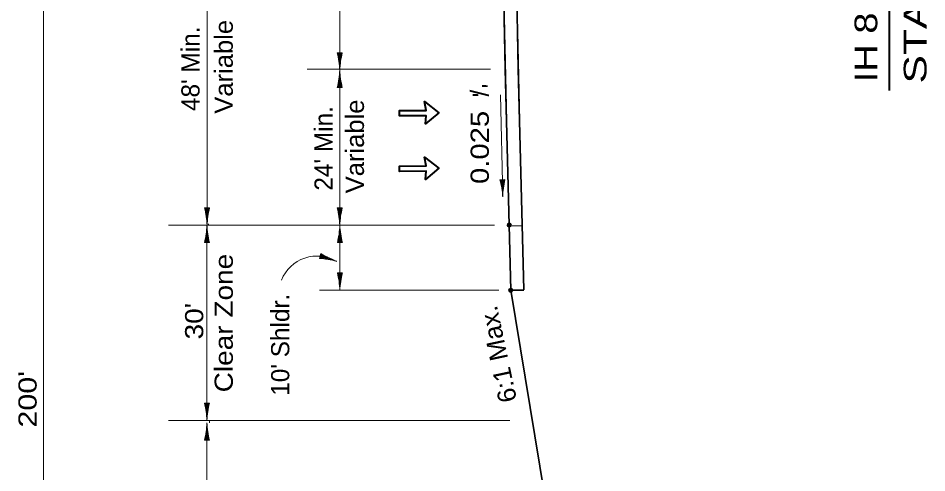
# Model space of a CAD drawing. Extents: x 2363427 to 2368559, y 6957299 to 6980140.
# Drawn here: x 2364676 to 2365376, y 6958581 to 6958931 of the extents above; entities that cross this region are included whole.
import ezdxf
from ezdxf.enums import TextEntityAlignment as Align

# ---------------------------------------------------------------- set-up
doc = ezdxf.new("R2010")
doc.units = 0
doc.header["$LTSCALE"] = 5.6
doc.header["$PDMODE"] = 32
doc.header["$PDSIZE"] = 2.8
for name, color, linetype, lineweight in [('3', 7, 'Continuous', 35), ('4', 7, 'Continuous', 13), ('40', 7, 'Continuous', 35), ('6', 7, 'Continuous', 13), ('8', 7, 'Continuous', 13)]:
    doc.layers.add(name, color=color, linetype=linetype, lineweight=lineweight)

msp = doc.modelspace()

# ---------------------------------------------------------------- linework, layer by layer
at = {"layer": '3'}
for p, q in [((2365057.76, 6959071.646), (2365061.35, 6958891.693)), ((2365061.348, 6958891.755), (2365064.48, 6958771.889)), ((2365054.484, 6958771.627), (2365055.653, 6958721.475)), ((2365064.481, 6958771.861), (2365065.65, 6958721.709)), ((2365065.653, 6958721.593), (2365055.65, 6958721.593)), ((2365055.653, 6958721.475), (2365118.982, 6958338.693))]:
    msp.add_line(p, q, dxfattribs=at)
at = {"layer": '3', "lineweight": 13}
for p, q in [((2365040.062, 6958891.447), (2364898.916, 6958891.447)), ((2365043.199, 6958771.447), (2364792.272, 6958771.447)), ((2365046.336, 6958721.447), (2364908.326, 6958721.447)), ((2365054.844, 6958621.447), (2364792.272, 6958621.447))]:
    msp.add_line(p, q, dxfattribs=at)
at = {"layer": '3'}
msp.add_lwpolyline([(2365047.761, 6959071.447), (2365051.351, 6958891.493), (2365054.484, 6958771.627)], dxfattribs=at)
at = {"layer": '3', "lineweight": 13}
for points in [[(2365054.483, 6958770.888), (2365064.398, 6958771.059), (2365058.919, 6959012.302), (2365048.975, 6959011.836)], [(2365055.653, 6958721.475), (2365065.65, 6958721.709), (2365064.398, 6958771.059), (2365054.483, 6958770.888)]]:
    msp.add_lwpolyline(points, close=True, dxfattribs=at)
msp.add_lwpolyline([(2365054.484, 6958771.627), (2365054.414, 6958771.773), (2365054.484, 6958771.627)], dxfattribs=at)
at = {"layer": '3'}
for p in [(2365054.484, 6958771.627), (2365055.653, 6958721.475)]:
    msp.add_point(p, dxfattribs=at)
at = {"layer": '4', "lineweight": 40}
msp.add_line((2365347.244, 6958874.931), (2365347.244, 6959337.074), dxfattribs=at)
at = {"layer": '4'}
for p, q in [((2365049.461, 6958793.173), (2365047.85, 6958871.793)), ((2365047.274, 6958806.443), (2365051.103, 6958806.521)), ((2365047.624, 6958806.449), (2365047.656, 6958804.865)), ((2365048.124, 6958806.461), (2365048.211, 6958802.185)), ((2365048.624, 6958806.471), (2365048.774, 6958799.123)), ((2365049.123, 6958806.481), (2365049.38, 6958793.919)), ((2365049.623, 6958806.491), (2365049.8, 6958797.883)), ((2365050.123, 6958806.501), (2365050.222, 6958801.641)), ((2365050.623, 6958806.511), (2365050.672, 6958804.131)), ((2364821.826, 6958758.135), (2364821.826, 6958770.699)), ((2364924.116, 6958758.135), (2364924.116, 6958770.699)), ((2364821.326, 6958758.135), (2364821.326, 6958766.745)), ((2364822.326, 6958758.135), (2364822.326, 6958765.485)), ((2364923.616, 6958758.135), (2364923.616, 6958766.745)), ((2364924.616, 6958758.135), (2364924.616, 6958765.485)), ((2364823.676, 6958758.135), (2364819.846, 6958758.135)), ((2364820.326, 6958758.135), (2364820.326, 6958760.517)), ((2364820.826, 6958758.135), (2364820.826, 6958762.997)), ((2364822.826, 6958758.135), (2364822.826, 6958762.411)), ((2364823.326, 6958758.135), (2364823.326, 6958759.72)), ((2364925.966, 6958758.135), (2364922.136, 6958758.135)), ((2364922.616, 6958758.135), (2364922.616, 6958760.517)), ((2364923.116, 6958758.135), (2364923.116, 6958762.997)), ((2364925.116, 6958758.135), (2364925.116, 6958762.411)), ((2364925.616, 6958758.135), (2364925.616, 6958759.72)), ((2364908.365, 6958745.982), (2364909.53, 6958749.631)), ((2364908.472, 6958746.315), (2364909.982, 6958745.833)), ((2364908.624, 6958746.792), (2364912.698, 6958745.491)), ((2364908.776, 6958747.268), (2364915.777, 6958745.031)), ((2364908.928, 6958747.745), (2364920.896, 6958743.921)), ((2364909.08, 6958748.221), (2364917.282, 6958745.601)), ((2364909.232, 6958748.697), (2364913.864, 6958747.217)), ((2364909.384, 6958749.173), (2364911.653, 6958748.449)), ((2364922.136, 6958734.758), (2364925.966, 6958734.758)), ((2364922.486, 6958734.758), (2364922.486, 6958733.173)), ((2364922.986, 6958734.758), (2364922.986, 6958730.481)), ((2364923.486, 6958734.758), (2364923.486, 6958727.408)), ((2364923.986, 6958734.758), (2364923.986, 6958722.194)), ((2364924.486, 6958734.758), (2364924.486, 6958726.149)), ((2364924.986, 6958734.758), (2364924.986, 6958729.896)), ((2364925.486, 6958734.758), (2364925.486, 6958732.377))]:
    msp.add_line(p, q, dxfattribs=at)
for centre, radius, start, end in [((2364977.426, 6958788.114), 72.212, 4.01743, 14.70348), ((2365121.643, 6958791.069), 72.212, 167.64427, 178.33032), ((2364749.638, 6958775.029), 72.212, 346.47039, 357.15644), ((2364893.885, 6958775.029), 72.212, 182.84356, 193.52961), ((2364851.928, 6958775.029), 72.212, 346.47039, 357.15644), ((2364996.175, 6958775.029), 72.212, 182.84356, 193.52961), ((2364946.989, 6958811.368), 72.212, 238.75343, 249.43948), ((2364906.608, 6958718.145), 29.635, 59.62074, 157.81619), ((2364903.092, 6958673.962), 72.212, 75.12659, 85.81264), ((2364851.928, 6958717.864), 72.212, 2.84356, 13.52961), ((2364996.175, 6958717.864), 72.212, 166.47039, 177.15644)]:
    msp.add_arc(centre, radius, start, end, dxfattribs=at)
at = {"layer": '40'}
for p, q in [((2364990.414, 6958855.675), (2364969.909, 6958855.479)), ((2364990.414, 6958812.985), (2364969.909, 6958812.79))]:
    msp.add_line(p, q, dxfattribs=at)
for points in [[(2364990.414, 6958855.675), (2364989.882, 6958849.359), (2365000.269, 6958857.895), (2364989.169, 6958866.497), (2364990.376, 6958859.769)], [(2364990.376, 6958859.769), (2364969.872, 6958859.575), (2364969.909, 6958855.479)], [(2364990.414, 6958812.985), (2364989.882, 6958806.67), (2365000.269, 6958815.205), (2364989.169, 6958823.807), (2364990.376, 6958817.08)], [(2364990.376, 6958817.08), (2364969.872, 6958816.885), (2364969.909, 6958812.79)]]:
    msp.add_lwpolyline(points, dxfattribs=at)
at = {"layer": '6'}
for p, q in [((2364695.934, 6958071.447), (2364695.934, 6959071.447)), ((2364821.862, 6958771.425), (2364821.862, 6959011.447)), ((2364923.994, 6958782.647), (2364923.994, 6959011.447)), ((2364922.08, 6958903.94), (2364925.91, 6958903.94)), ((2364922.43, 6958903.94), (2364922.43, 6958902.355)), ((2364922.93, 6958903.94), (2364922.93, 6958899.663)), ((2364923.43, 6958903.94), (2364923.43, 6958896.59)), ((2364923.93, 6958903.94), (2364923.93, 6958891.376)), ((2364924.43, 6958903.94), (2364924.43, 6958895.331)), ((2364924.93, 6958903.94), (2364924.93, 6958899.078)), ((2364925.43, 6958903.94), (2364925.43, 6958901.559)), ((2364924.06, 6958877.317), (2364924.06, 6958889.881)), ((2364923.56, 6958877.317), (2364923.56, 6958885.927)), ((2364924.56, 6958877.317), (2364924.56, 6958884.667)), ((2364925.91, 6958877.317), (2364922.08, 6958877.317)), ((2364922.56, 6958877.317), (2364922.56, 6958879.699)), ((2364923.06, 6958877.317), (2364923.06, 6958882.179)), ((2364925.06, 6958877.317), (2364925.06, 6958881.593)), ((2364925.56, 6958877.317), (2364925.56, 6958878.902)), ((2364819.947, 6958784.736), (2364823.777, 6958784.736)), ((2364820.297, 6958784.736), (2364820.297, 6958783.151)), ((2364820.797, 6958784.736), (2364820.797, 6958780.459)), ((2364821.297, 6958784.736), (2364821.297, 6958777.386)), ((2364821.797, 6958784.736), (2364821.797, 6958772.172)), ((2364822.297, 6958784.736), (2364822.297, 6958776.127)), ((2364822.797, 6958784.736), (2364822.797, 6958779.874)), ((2364823.297, 6958784.736), (2364823.297, 6958782.355)), ((2364922.08, 6958784.736), (2364925.91, 6958784.736)), ((2364922.43, 6958784.736), (2364922.43, 6958783.151)), ((2364922.93, 6958784.736), (2364922.93, 6958780.459)), ((2364923.43, 6958784.736), (2364923.43, 6958777.386)), ((2364923.93, 6958784.736), (2364923.93, 6958772.172)), ((2364924.43, 6958784.736), (2364924.43, 6958776.127)), ((2364924.93, 6958784.736), (2364924.93, 6958779.874)), ((2364925.43, 6958784.736), (2364925.43, 6958782.355)), ((2364821.762, 6958621.447), (2364821.762, 6958771.447)), ((2364822.936, 6958771.265), (2364822.936, 6958772.455)), ((2364924.052, 6958721.447), (2364924.052, 6958771.447)), ((2364819.846, 6958634.758), (2364823.676, 6958634.758)), ((2364820.196, 6958634.758), (2364820.196, 6958633.173)), ((2364820.696, 6958634.758), (2364820.696, 6958630.481)), ((2364821.196, 6958634.758), (2364821.196, 6958627.408)), ((2364821.696, 6958634.758), (2364821.696, 6958622.194)), ((2364822.196, 6958634.758), (2364822.196, 6958626.149)), ((2364822.696, 6958634.758), (2364822.696, 6958629.896)), ((2364823.196, 6958634.758), (2364823.196, 6958632.377)), ((2364821.74, 6958619.485), (2364821.74, 6958338.693)), ((2364821.805, 6958606.175), (2364821.805, 6958618.739)), ((2364823.782, 6958621.507), (2364823.782, 6958619.485)), ((2364820.805, 6958606.175), (2364820.805, 6958611.037)), ((2364821.305, 6958606.175), (2364821.305, 6958614.783)), ((2364822.305, 6958606.175), (2364822.305, 6958613.525)), ((2364822.805, 6958606.175), (2364822.805, 6958610.451)), ((2364823.655, 6958606.175), (2364819.825, 6958606.175)), ((2364820.305, 6958606.175), (2364820.305, 6958608.555)), ((2364823.305, 6958606.175), (2364823.305, 6958607.759))]:
    msp.add_line(p, q, dxfattribs=at)
for centre, start, end in [((2364851.871, 6958887.046), 2.84356, 13.52961), ((2364996.118, 6958887.046), 166.47039, 177.15644), ((2364851.871, 6958894.211), 346.47039, 357.15644), ((2364996.118, 6958894.211), 182.84356, 193.52961), ((2364749.738, 6958767.842), 2.84356, 13.52961), ((2364893.986, 6958767.842), 166.47039, 177.15644), ((2364851.871, 6958767.842), 2.84356, 13.52961), ((2364996.118, 6958767.842), 166.47039, 177.15644), ((2364749.638, 6958617.864), 2.84356, 13.52961), ((2364893.885, 6958617.864), 166.47039, 177.15644), ((2364749.616, 6958623.068), 346.47039, 357.15644), ((2364893.864, 6958623.068), 182.84356, 193.52961)]:
    msp.add_arc(centre, 72.212, start, end, dxfattribs=at)
at = {"layer": '8', "lineweight": 40}
for points in [[(2365000.269, 6958857.895), (2364989.882, 6958849.359), (2364990.414, 6958855.675), (2364969.909, 6958855.479), (2364969.872, 6958859.575), (2364990.376, 6958859.769), (2364989.169, 6958866.497)], [(2365000.269, 6958815.205), (2364989.882, 6958806.67), (2364990.414, 6958812.985), (2364969.909, 6958812.79), (2364969.872, 6958816.885), (2364990.376, 6958817.08), (2364989.169, 6958823.807)]]:
    msp.add_lwpolyline(points, close=True, dxfattribs=at)

# ---------------------------------------------------------------- texts
at = {"layer": '4'}
for s, height, rotation, width, p in [('IH 820 WITH FRONTAGE ROADS', 17.5, 90, 1.25, (2365337.76, 6959107.242)), ('STA. 757+00 TO STA. 769+00', 17.5, 90, 1.4, (2365375.66, 6959104.418)), ('Variable', 14, 90, 1.05, (2364841.668, 6958893.23)), ('Variable', 14, 90, 1.05, (2364942.629, 6958832.038)), ('0.025', 14, 90, 1.2, (2365038.744, 6958831.293)), ('Clear Zone', 14, 90, 1.15, (2364841.668, 6958696.266)), ("30'", 14, 90, 1.15, (2364818.902, 6958697.698)), ('6:1 Max.', 14, 101.975, 1.05, (2365052.679, 6958673.705)), ("200'", 14, 90, 1.25, (2364690.637, 6958637.675))]:
    msp.add_text(s, height=height, rotation=rotation, dxfattribs=dict(at, width=width)).set_placement(p, align=Align.CENTER)
for s, p in [("48' Min.", (2364816.052, 6958891.73)), ('/', (2365038.744, 6958872.979)), ("'", (2365047.37, 6958878.431)), ("'", (2365040.347, 6958871.545)), ("24' Min.", (2364918.519, 6958830.541)), ("10' Shldr.", (2364885.132, 6958679.624))]:
    msp.add_text(s, height=14, rotation=90, dxfattribs=at).set_placement(p, align=Align.CENTER)

doc.saveas('drawing.dxf')
